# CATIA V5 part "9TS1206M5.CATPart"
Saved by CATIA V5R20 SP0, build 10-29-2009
Part number: 9TS1206M5
Revision: ANY
Definition: UNKNOWN
Nomenclature: 9TS1206M5
Source: Unknown
Bounding box of the stored display mesh (mm): x -6 to 6, y -5.85 to 5.85, z 0 to 6
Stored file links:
  C:\Users\Utente\Desktop\IO LAVORO\3D X SITO CF\CUMSA\3D files GR\GR 182622-10\9TS1206M5.CATPart
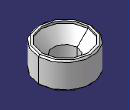
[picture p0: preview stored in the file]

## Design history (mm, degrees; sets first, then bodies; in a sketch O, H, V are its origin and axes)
Body1 "Chaflán2" (main body)
  Solid1: solid without history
